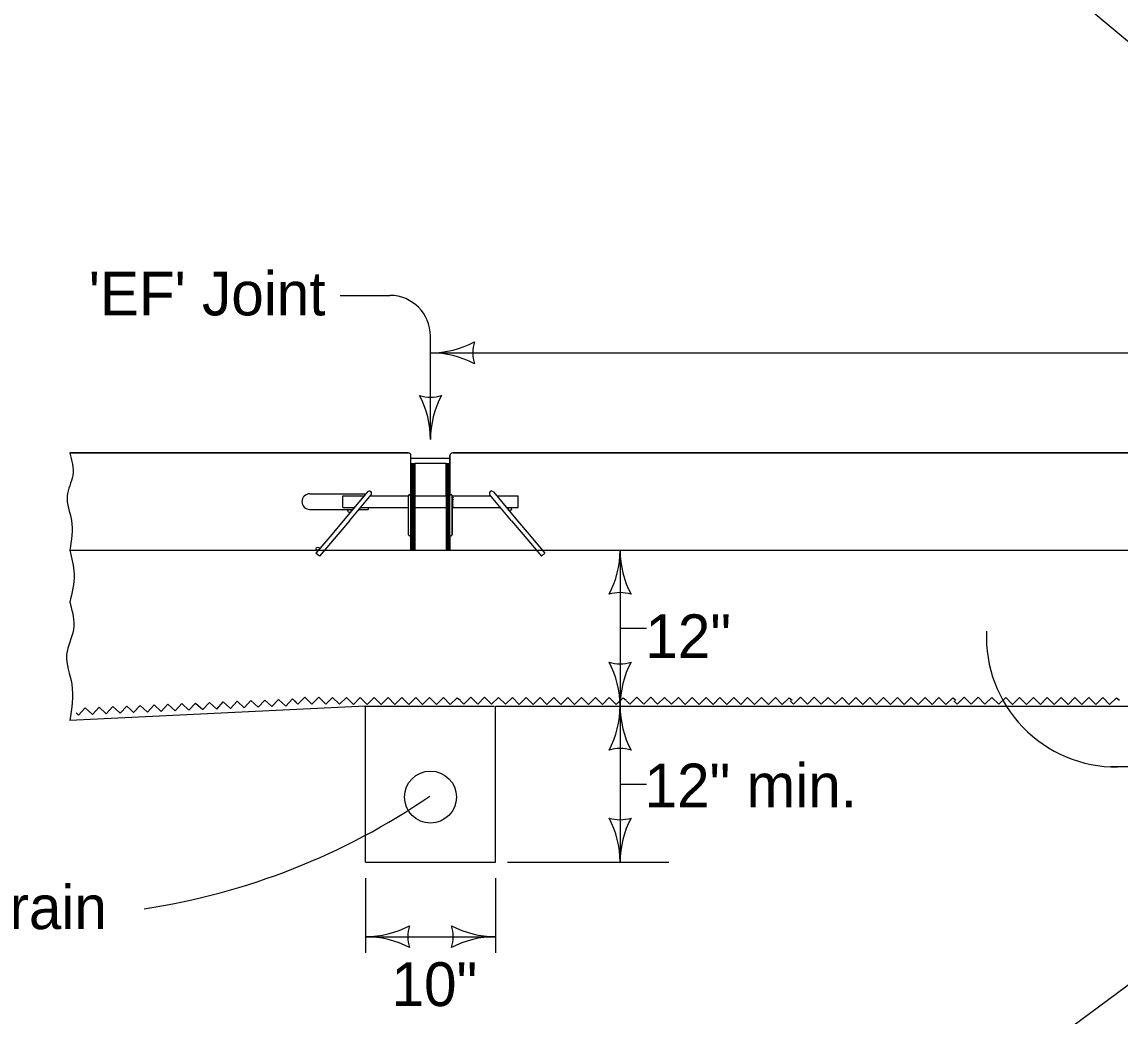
# Model space of a CAD drawing. Extents: x 8925 to 81668, y 4369 to 11918.
# Drawn here: x 14467 to 14969, y 5831 to 6286 of the extents above; entities that cross this region are included whole.
import ezdxf

# ---------------------------------------------------------------- set-up
doc = ezdxf.new("R2010")
doc.units = 0
for name, color, linetype in [('dsnShtPlotShapeBatchPrint', 7, 'Continuous'), ('dsnStdBorder', 7, 'Continuous'), ('SheetBorder', 7, 'Continuous')]:
    doc.layers.add(name, color=color, linetype=linetype)

msp = doc.modelspace()

# ---------------------------------------------------------------- linework, layer by layer
at = {"layer": 'dsnStdBorder'}
for p, q in [((14612.03, 6160.84), (14634.82, 6160.84)), ((14653.38, 6127.34), (14653.38, 6142.27)), ((14653.38, 6134.57), (15580.02, 6134.57)), ((14653.38, 6094.95), (14653.38, 6127.34)), ((14643.22, 6088.81), (14488.38, 6088.81)), ((14488.38, 6088.81), (14643.22, 6088.81)), ((15580.02, 6088.81), (14663.54, 6088.81)), ((14663.54, 6088.81), (15580.02, 6088.81)), ((14644.47, 6069.25), (14644.47, 6087.57)), ((14644.47, 6057.81), (14644.47, 6087.56)), ((14644.47, 6086.4), (14662.29, 6086.4)), ((14644.47, 6084), (14646.25, 6084)), ((14644.65, 6084), (14644.65, 6057.81)), ((14644.83, 6084), (14644.83, 6057.81)), ((14645, 6084), (14645, 6057.81)), ((14645.18, 6084), (14645.18, 6057.81)), ((14645.36, 6084), (14645.36, 6057.81)), ((14645.54, 6084), (14645.54, 6057.81)), ((14645.72, 6084), (14645.72, 6057.81)), ((14645.9, 6084), (14645.9, 6057.81)), ((14646.07, 6084), (14646.07, 6057.81)), ((14660.51, 6084), (14646.25, 6084)), ((14646.25, 6084), (14646.25, 6069.21)), ((14660.51, 6069.21), (14660.51, 6084)), ((14660.51, 6084), (14662.29, 6084)), ((14660.69, 6084), (14660.69, 6057.81)), ((14660.86, 6084), (14660.86, 6057.81)), ((14661.04, 6084), (14661.04, 6057.81)), ((14661.22, 6084), (14661.22, 6057.81)), ((14661.4, 6084), (14661.4, 6057.81)), ((14661.58, 6084), (14661.58, 6057.81)), ((14661.76, 6084), (14661.76, 6057.81)), ((14661.93, 6084), (14661.93, 6057.81)), ((14662.11, 6084), (14662.11, 6057.81)), ((14662.29, 6087.56), (14662.29, 6069.21)), ((14662.29, 6057.81), (14662.29, 6087.56)), ((14598.14, 6070.1), (14623.83, 6070.1)), ((14613.28, 6063.86), (14613.28, 6069.21)), ((14613.28, 6069.21), (14623.09, 6069.21)), ((14624.56, 6070.97), (14613.52, 6057.81)), ((14616.31, 6057.81), (14626.2, 6069.59)), ((14625.88, 6069.21), (14643.4, 6069.21)), ((14643.4, 6051.39), (14643.4, 6069.21)), ((14643.4, 6051.39), (14643.4, 6069.21)), ((14646.25, 6069.21), (14646.25, 6063.86)), ((14646.25, 6069.21), (14660.51, 6069.21)), ((14660.51, 6069.21), (14660.51, 6063.86)), ((14663.36, 6069.21), (14663.36, 6051.39)), ((14663.36, 6051.39), (14663.36, 6069.21)), ((14663.36, 6069.21), (14680.88, 6069.21)), ((14690.45, 6057.81), (14680.56, 6069.59)), ((14682.2, 6070.97), (14693.24, 6057.81)), ((14683.67, 6069.21), (14693.47, 6069.21)), ((14693.47, 6063.86), (14693.47, 6069.21)), ((14598.14, 6062.97), (14617.85, 6062.97)), ((14613.28, 6063.86), (14618.6, 6063.86)), ((14620.65, 6062.97), (14624.87, 6062.97)), ((14621.39, 6063.86), (14643.4, 6063.86)), ((14624.87, 6063.86), (14624.87, 6062.97)), ((14646.25, 6063.86), (14660.51, 6063.86)), ((14646.25, 6063.86), (14646.25, 6057.81)), ((14660.51, 6063.86), (14660.51, 6057.81)), ((14663.36, 6063.86), (14685.37, 6063.86)), ((14688.16, 6063.86), (14693.47, 6063.86)), ((14613.52, 6057.81), (14608.26, 6051.54)), ((14616.31, 6057.81), (14611.05, 6051.54)), ((14644.47, 6051.54), (14644.47, 6057.81)), ((14644.65, 6057.81), (14644.65, 6051.54)), ((14644.83, 6057.81), (14644.83, 6051.54)), ((14645, 6057.81), (14645, 6051.54)), ((14645.18, 6057.81), (14645.18, 6051.54)), ((14645.36, 6057.81), (14645.36, 6051.54)), ((14645.54, 6057.81), (14645.54, 6051.54)), ((14645.72, 6057.81), (14645.72, 6051.54)), ((14645.9, 6057.81), (14645.9, 6051.54)), ((14646.07, 6057.81), (14646.07, 6051.54)), ((14646.25, 6057.81), (14646.25, 6051.54)), ((14660.51, 6057.81), (14660.51, 6051.54)), ((14660.69, 6057.81), (14660.69, 6051.54)), ((14660.86, 6057.81), (14660.86, 6051.54)), ((14661.04, 6057.81), (14661.04, 6051.54)), ((14661.22, 6057.81), (14661.22, 6051.54)), ((14661.4, 6057.81), (14661.4, 6051.54)), ((14661.58, 6057.81), (14661.58, 6051.54)), ((14661.76, 6057.81), (14661.76, 6051.54)), ((14661.93, 6057.81), (14661.93, 6051.54)), ((14662.11, 6057.81), (14662.11, 6051.54)), ((14662.29, 6051.54), (14662.29, 6057.81)), ((14690.45, 6057.81), (14695.71, 6051.54)), ((14693.24, 6057.81), (14698.5, 6051.54)), ((14608.26, 6051.54), (14601.01, 6042.9)), ((14611.05, 6051.54), (14602.65, 6041.53)), ((14644.47, 6044.26), (14644.47, 6051.54)), ((14644.47, 6044.26), (14644.47, 6051.35)), ((14644.65, 6051.54), (14644.65, 6044.26)), ((14644.83, 6051.54), (14644.83, 6044.26)), ((14645, 6051.54), (14645, 6044.26)), ((14645.18, 6051.54), (14645.18, 6044.26)), ((14645.36, 6051.54), (14645.36, 6044.26)), ((14645.54, 6051.54), (14645.54, 6044.26)), ((14645.72, 6051.54), (14645.72, 6044.26)), ((14645.9, 6051.54), (14645.9, 6044.26)), ((14646.07, 6051.54), (14646.07, 6044.26)), ((14646.25, 6051.54), (14646.25, 6044.26)), ((14660.51, 6051.54), (14660.51, 6044.26)), ((14660.69, 6051.54), (14660.69, 6044.26)), ((14660.86, 6051.54), (14660.86, 6044.26)), ((14661.04, 6051.54), (14661.04, 6044.26)), ((14661.22, 6051.54), (14661.22, 6044.26)), ((14661.4, 6051.54), (14661.4, 6044.26)), ((14661.58, 6051.54), (14661.58, 6044.26)), ((14661.76, 6051.54), (14661.76, 6044.26)), ((14661.93, 6051.54), (14661.93, 6044.26)), ((14662.11, 6051.54), (14662.11, 6044.26)), ((14662.29, 6044.26), (14662.29, 6051.54)), ((14662.29, 6051.39), (14662.29, 6044.26)), ((14695.71, 6051.54), (14704.11, 6041.53)), ((14698.5, 6051.54), (14705.75, 6042.9)), ((14488.38, 6044.26), (14604.94, 6044.26)), ((14488.38, 6044.26), (14602.15, 6044.26)), ((14602.65, 6041.53), (14601.01, 6042.9)), ((14604.94, 6044.26), (14644.47, 6044.26)), ((14604.94, 6044.26), (14646.25, 6044.26)), ((14646.25, 6044.26), (14660.51, 6044.26)), ((14660.51, 6044.26), (14701.82, 6044.26)), ((14662.29, 6044.26), (14704.61, 6044.26)), ((14704.11, 6041.53), (14705.75, 6042.9)), ((14704.61, 6044.26), (15580.02, 6044.26)), ((14704.61, 6044.26), (15580.02, 6044.26)), ((14740.12, 6044.26), (14740.12, 5972.98)), ((14740.12, 6008.62), (14752.24, 6008.62)), ((14623.68, 5972.98), (14488.37, 5966.43)), ((14623.06, 5972.98), (14682.46, 5972.98)), ((14623.68, 5901.7), (14623.68, 5972.98)), ((14683.08, 5972.98), (15580.02, 5972.98)), ((14683.08, 5901.7), (14683.08, 5972.98)), ((14740.12, 5972.98), (14740.12, 5901.7)), ((14998.94, 5945.25), (14964.38, 5945.25)), ((14740.12, 5937.34), (14752.24, 5937.34)), ((14623.68, 5901.7), (14683.08, 5901.7)), ((14688.66, 5901.7), (14762.45, 5901.7)), ((14623.68, 5894.27), (14623.68, 5860.12)), ((14683.08, 5894.27), (14683.08, 5860.12)), ((14623.68, 5867.54), (14683.08, 5867.54))]:
    msp.add_line(p, q, dxfattribs=at)
for points in [[(14662.29, 6069.21), (14662.29, 6069.21)], [(14646.25, 6063.57), (14646.55, 6063.86)], [(14662.29, 6051.39), (14662.29, 6051.39)], [(14491.27, 5969.97), (14492.43, 5968.91), (14495.46, 5972.21), (14498.76, 5969.18), (14501.8, 5972.49), (14505.09, 5969.46), (14508.13, 5972.76), (14511.43, 5969.73), (14514.45, 5973.02), (14516.1, 5971.52)], [(14515.95, 5971.54), (14517.6, 5970.03), (14520.62, 5973.32), (14523.92, 5970.29), (14526.96, 5973.61), (14530.25, 5970.57), (14533.28, 5973.87), (14536.59, 5970.85), (14539.61, 5974.14), (14542.91, 5971.12), (14545.95, 5974.42), (14549.24, 5971.39), (14552.27, 5974.7), (14555.58, 5971.67), (14558.6, 5974.97), (14561.9, 5971.94), (14564.93, 5975.24), (14568.23, 5972.21), (14571.26, 5975.52), (14574.56, 5972.48), (14577.6, 5975.79), (14580.89, 5972.77), (14583.93, 5976.06), (14587.23, 5973.04), (14590.25, 5976.33), (14591.9, 5974.82)], [(14591.19, 5975.47), (14592.77, 5973.88), (14595.95, 5977.04), (14599.1, 5973.86), (14602.29, 5977.02), (14605.45, 5973.84), (14608.61, 5977), (14611.78, 5973.82), (14614.96, 5976.98), (14618.11, 5973.8), (14621.29, 5976.97), (14624.45, 5973.79), (14627.63, 5976.95), (14630.78, 5973.77), (14633.97, 5976.93), (14637.13, 5973.76), (14640.29, 5976.92), (14643.46, 5973.74), (14646.63, 5976.9), (14649.79, 5973.73), (14652.97, 5976.88), (14656.13, 5973.71), (14659.3, 5976.87), (14662.46, 5973.69), (14665.64, 5976.85), (14667.06, 5975.72)], [(14667.06, 5975.47), (14668.64, 5973.88), (14671.82, 5977.04), (14674.97, 5973.86), (14678.16, 5977.02), (14681.32, 5973.84), (14684.48, 5977), (14687.64, 5973.82), (14690.83, 5976.98), (14693.98, 5973.8), (14697.16, 5976.97), (14700.32, 5973.79), (14703.5, 5976.95), (14706.65, 5973.77), (14709.84, 5976.93), (14713, 5973.76), (14716.16, 5976.92), (14719.32, 5973.74), (14722.5, 5976.9), (14725.66, 5973.73), (14728.84, 5976.88), (14732, 5973.71), (14735.17, 5976.87), (14738.33, 5973.69), (14741.51, 5976.85), (14742.93, 5975.72)], [(14743.03, 5975.47), (14744.61, 5973.88), (14747.79, 5977.04), (14750.94, 5973.86), (14754.12, 5977.02), (14757.28, 5973.84), (14760.45, 5977), (14763.61, 5973.82), (14766.8, 5976.98), (14769.95, 5973.8), (14773.13, 5976.97), (14776.29, 5973.79), (14779.47, 5976.95), (14782.62, 5973.77), (14785.8, 5976.93), (14788.96, 5973.76), (14792.13, 5976.92), (14795.29, 5973.74), (14798.47, 5976.9), (14801.63, 5973.73), (14804.81, 5976.88), (14807.97, 5973.71), (14811.14, 5976.87), (14814.3, 5973.69), (14817.48, 5976.85), (14818.9, 5975.72)], [(14817.87, 5975.47), (14819.45, 5973.88), (14822.63, 5977.04), (14825.78, 5973.86), (14828.97, 5977.02), (14832.13, 5973.84), (14835.3, 5977), (14838.46, 5973.82), (14841.64, 5976.98), (14844.79, 5973.8), (14847.98, 5976.97), (14851.14, 5973.79), (14854.31, 5976.95), (14857.46, 5973.77), (14860.65, 5976.93), (14863.81, 5973.76), (14866.98, 5976.92), (14870.14, 5973.74), (14873.31, 5976.9), (14876.47, 5973.73), (14879.66, 5976.88), (14882.81, 5973.71), (14885.98, 5976.87), (14889.14, 5973.69), (14892.32, 5976.85), (14893.75, 5975.72)], [(14892.76, 5975.47), (14894.34, 5973.88), (14897.52, 5977.04), (14900.68, 5973.86), (14903.86, 5977.02), (14907.02, 5973.84), (14910.19, 5977), (14913.35, 5973.82), (14916.53, 5976.98), (14919.68, 5973.8), (14922.87, 5976.97), (14926.03, 5973.79), (14929.2, 5976.95), (14932.36, 5973.77), (14935.54, 5976.93), (14938.7, 5973.76), (14941.87, 5976.92), (14945.03, 5973.74), (14948.2, 5976.9), (14951.36, 5973.73), (14954.55, 5976.88), (14957.7, 5973.71), (14960.87, 5976.87), (14964.04, 5973.69), (14967.21, 5976.85), (14968.64, 5975.72)]]:
    msp.add_lwpolyline(points, dxfattribs=at)
for centre, radius in [((14616.33, 6062.26), 0.713), ((14689.69, 6063.15), 0.713), ((14601.82, 6044.98), 0.713), ((14653.38, 5931.4), 11.88)]:
    msp.add_circle(centre, radius, dxfattribs=at)
for centre, radius, start, end in [((14634.82, 6142.28), 18.56, 0, 90), ((14653.38, 6177.32), 42.75, 270, 298.0725), ((14689.22, 6134.58), 16.51, 162.2666, 197.7334), ((14653.38, 6091.83), 42.75, 61.9275, 90), ((14653.38, 6130.8), 16.51, 252.2666, 287.7333), ((14610.63, 6094.96), 42.75, 360, 28.0725), ((14696.13, 6094.96), 42.75, 151.9275, 180), ((14643.22, 6087.57), 1.25, 360, 90), ((14643.22, 6087.57), 1.25, 0, 90), ((14663.54, 6087.56), 1.25, 90, 180), ((14663.54, 6087.57), 1.25, 90, 180), ((14598.14, 6066.54), 3.56, 90, 270), ((14625.38, 6070.28), 1.07, 320.0037, 139.9964), ((14643.94, 6069.21), 0.535, 3.7252, 180), ((14643.94, 6069.21), 0.535, 0, 180), ((14662.83, 6069.21), 0.535, 0, 180), ((14662.82, 6069.21), 0.535, 0, 180), ((14681.38, 6070.28), 1.07, 40.0036, 219.9963), ((14643.94, 6051.39), 0.535, 180, 355.2519), ((14643.94, 6051.39), 0.535, 180, 0), ((14662.82, 6051.39), 0.535, 180, 0), ((14662.83, 6051.39), 0.535, 180, 0), ((14697.37, 6044.26), 42.75, 331.9275, 360), ((14697.37, 6044.26), 42.75, 331.9275, 360), ((14782.87, 6044.26), 42.75, 180, 208.0725), ((14782.87, 6044.26), 42.75, 180, 208.0725), ((14740.12, 6008.42), 16.51, 72.2666, 107.7334), ((14740.12, 6008.42), 16.51, 72.2666, 107.7334), ((14967.09, 6004.6), 59.4, 177.3942, 270.5267), ((14740.12, 6008.83), 16.51, 252.2666, 287.7333), ((14697.37, 5972.98), 42.75, 360, 28.0725), ((14740.12, 6008.83), 16.51, 252.2666, 287.7333), ((14697.37, 5972.98), 42.75, 360, 28.0725), ((14782.87, 5972.98), 42.75, 151.9275, 180), ((14782.87, 5972.98), 42.75, 151.9275, 180), ((14697.37, 5972.98), 42.75, 331.9275, 360), ((14697.37, 5972.98), 42.75, 331.9275, 360), ((14782.87, 5972.98), 42.75, 180, 208.0725), ((14782.87, 5972.98), 42.75, 180, 208.0725), ((14740.12, 5937.14), 16.51, 72.2666, 107.7334), ((14740.12, 5937.14), 16.51, 72.2666, 107.7334), ((14475.44, 6191.21), 314.4, 278.602, 304.4007), ((14740.12, 5937.55), 16.51, 252.2666, 287.7333), ((14697.37, 5901.7), 42.75, 360, 28.0725), ((14740.12, 5937.55), 16.51, 252.2666, 287.7333), ((14697.37, 5901.7), 42.75, 360, 28.0725), ((14782.87, 5901.7), 42.75, 151.9275, 180), ((14782.87, 5901.7), 42.75, 151.9275, 180), ((14623.68, 5910.3), 42.75, 270, 298.0725), ((14623.68, 5910.3), 42.75, 270, 298.0725), ((14659.52, 5867.55), 16.51, 162.2666, 197.7334), ((14659.52, 5867.55), 16.51, 162.2666, 197.7334), ((14647.24, 5867.55), 16.51, 342.2666, 17.7333), ((14683.08, 5910.3), 42.75, 241.9275, 270), ((14647.24, 5867.55), 16.51, 342.2666, 17.7333), ((14683.08, 5910.3), 42.75, 241.9275, 270), ((14623.68, 5824.8), 42.75, 61.9275, 90), ((14623.68, 5824.8), 42.75, 61.9275, 90), ((14683.08, 5824.8), 42.75, 90, 118.0725), ((14683.08, 5824.8), 42.75, 90, 118.0725)]:
    msp.add_arc(centre, radius, start, end, dxfattribs=at)
for points in [[(14488.38, 6088.81), (14489.74, 6078.52), (14487.17, 6069.14), (14489.13, 6057.96), (14488.38, 6044.26)], [(14488.38, 6088.81), (14489.74, 6078.52), (14487.17, 6069.14), (14489.13, 6057.96), (14488.38, 6044.26)], [(14663.36, 6068.85), (14663.45, 6068.85), (14663.54, 6068.86), (14663.62, 6068.85), (14663.68, 6068.86), (14663.74, 6068.84), (14663.79, 6068.85)], [(14663.36, 6068.5), (14663.45, 6068.49), (14663.54, 6068.5), (14663.62, 6068.49), (14663.68, 6068.51), (14663.74, 6068.49), (14663.79, 6068.49)], [(14663.36, 6068.14), (14663.45, 6068.13), (14663.54, 6068.15), (14663.62, 6068.13), (14663.68, 6068.15), (14663.74, 6068.13), (14663.79, 6068.14)], [(14663.36, 6067.78), (14663.45, 6067.78), (14663.54, 6067.79), (14663.62, 6067.78), (14663.68, 6067.79), (14663.74, 6067.77), (14663.79, 6067.78)], [(14663.36, 6067.43), (14663.45, 6067.42), (14663.54, 6067.43), (14663.62, 6067.42), (14663.68, 6067.44), (14663.74, 6067.42), (14663.79, 6067.43)], [(14663.36, 6067.07), (14663.45, 6067.06), (14663.54, 6067.08), (14663.62, 6067.06), (14663.68, 6067.08), (14663.74, 6067.06), (14663.79, 6067.07)], [(14663.36, 6066.72), (14663.45, 6066.71), (14663.54, 6066.72), (14663.62, 6066.71), (14663.68, 6066.72), (14663.74, 6066.7), (14663.79, 6066.71)], [(14663.36, 6066.36), (14663.45, 6066.35), (14663.54, 6066.36), (14663.62, 6066.35), (14663.68, 6066.37), (14663.74, 6066.35), (14663.79, 6066.36)], [(14663.36, 6066), (14663.45, 6066), (14663.54, 6066.01), (14663.62, 6066), (14663.68, 6066.01), (14663.74, 6065.99), (14663.79, 6066)], [(14663.36, 6065.65), (14663.45, 6065.64), (14663.54, 6065.65), (14663.62, 6065.64), (14663.68, 6065.65), (14663.74, 6065.63), (14663.79, 6065.64)], [(14663.36, 6065.29), (14663.45, 6065.28), (14663.54, 6065.29), (14663.62, 6065.28), (14663.68, 6065.3), (14663.74, 6065.28), (14663.79, 6065.29)], [(14663.36, 6064.93), (14663.45, 6064.93), (14663.54, 6064.94), (14663.62, 6064.93), (14663.68, 6064.94), (14663.74, 6064.92), (14663.79, 6064.93)], [(14663.36, 6064.58), (14663.45, 6064.57), (14663.54, 6064.58), (14663.62, 6064.57), (14663.68, 6064.59), (14663.74, 6064.57), (14663.79, 6064.57)], [(14663.36, 6064.22), (14663.45, 6064.21), (14663.54, 6064.23), (14663.62, 6064.21), (14663.68, 6064.23), (14663.74, 6064.21), (14663.79, 6064.22)], [(14488.38, 6044.26), (14490.34, 6033.32), (14488.38, 6020.5)], [(14488.38, 6020.5), (14490.03, 6007.99), (14486.91, 5996.6), (14489.29, 5983), (14488.38, 5966.35)]]:
    msp.add_spline(points, degree=3, dxfattribs=at)
at = {"layer": 'SheetBorder'}
for p, q in [((13555.2, 7461.71), (17208.84, 4407.74)), ((17092.54, 7422.93), (13574.58, 4805.24))]:
    msp.add_line(p, q, dxfattribs=at)

# ---------------------------------------------------------------- texts
at = {"layer": 'dsnShtPlotShapeBatchPrint'}
for s, p in [("'EF' Joint", (14497.07, 6151.7)), ('12"', (14751.66, 5994.96)), ('12" min.', (14751.3, 5926.71)), ('4" Perforated Subdrain', (14234.21, 5871)), ('10"', (14635.56, 5835.82))]:
    msp.add_text(s, height=20, dxfattribs=at).set_placement(p)

doc.saveas('drawing.dxf')
